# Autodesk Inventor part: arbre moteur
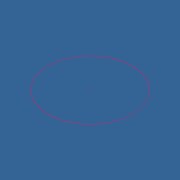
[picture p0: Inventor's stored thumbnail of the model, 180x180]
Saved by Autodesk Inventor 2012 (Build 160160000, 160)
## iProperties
Created: 2011-10
Part Number: arbre moteur
Material: Acier allié
Document SubType Name: Modeling
Designer: Laur
Mass: 0.147044 g
Surface Area: 0.534856 cm^2
Volume: 0.0187317 cm^3
Density: 7.85 g/cm^3
Author: Laur
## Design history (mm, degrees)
sketch "Esquisse1"
  geometry: C1 r 0.75 at (0, 0) reference
  dimensions: "d0" = 10.6 dimension on C1.centre C1
extrude "Extrusion1" new body sketch "Esquisse1" stored distance "d0" = 10.6; taper "d1" = 0 deg
node "Solide1"
node "Corps solides"
node "Corps surfaciques"
node "Référence1"
